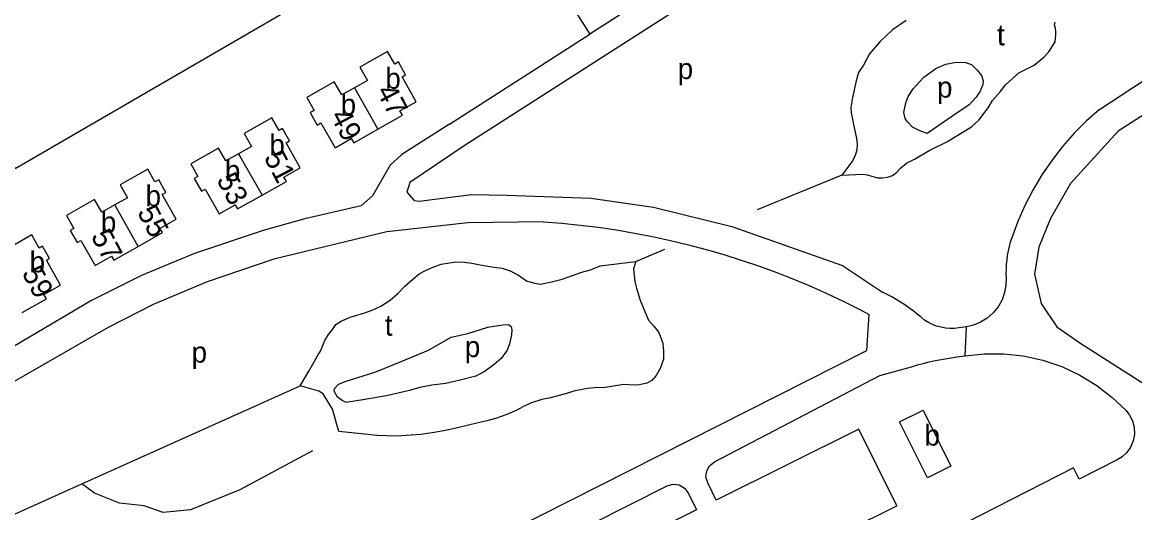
# Model space of a CAD drawing. Extents: x 158142 to 159655, y 385262 to 387204.
# Drawn here: x 158843.1 to 159056.3, y 386567 to 386661 of the extents above; entities that cross this region are included whole.
import ezdxf

# ---------------------------------------------------------------- set-up
doc = ezdxf.new("R2010")
doc.units = 0
for name, color, linetype in [('BLT_Basislijn', 7, 'Continuous'), ('BLT_Bebouwing', 7, 'Continuous'), ('BLT_Centroide', 7, 'Continuous'), ('BLT_Huisnummer', 7, 'Continuous'), ('BLT_Huisnummer_ tussenligend', 7, 'Continuous'), ('BLT_Onderverdeling_panden', 7, 'Continuous'), ('BLT_Vlakafsluiter', 7, 'Continuous')]:
    doc.layers.add(name, color=color, linetype=linetype)

msp = doc.modelspace()

# ---------------------------------------------------------------- linework, layer by layer
at = {"layer": 'BLT_Basislijn'}
for p, q in [((158962.1, 386665.28), (158951.94, 386658.76)), ((158925.01, 386641.49), (158951.94, 386658.76)), ((159000.23, 386631.69), (158983.98, 386625.1)), ((158960.72, 386615.19), (158966.31, 386617.55)), ((158854.55, 386572.55), (158896.42, 386591.34)), ((158826.78, 386560.1), (158854.55, 386572.55))]:
    msp.add_line(p, q, dxfattribs=at)
for points in [[(159032.59, 386711.15), (159035.58, 386706.39), (158927.86, 386637.32), (158917.44, 386630.31), (158916.87, 386628.46), (158918.23, 386626.84), (158919.19, 386626.73), (158929.27, 386628.01), (158936.03, 386627.86), (158952.13, 386627.33), (158964.14, 386625.61), (158979.12, 386621.87), (159000.33, 386614.38), (159008.02, 386609.31)], [(158800.5, 386644.91), (158826.35, 386660.11), (158841.79, 386632.99), (158934.18, 386686.67), (158951.94, 386658.76)], [(159049.58, 386644.33), (159081.97, 386665.65), (159105.75, 386680.86), (159110.71, 386684.88)], [(159012.56, 386661.36), (159009.93, 386659.58), (159007.5, 386657.27), (159005.54, 386654.96), (159004.35, 386652.83), (159003.4, 386651.37), (159002.96, 386649.79), (159002.25, 386646.61), (159001.96, 386644.66), (159002.03, 386643.66), (159002.17, 386642.74), (159002.37, 386641.76), (159003.04, 386638.74), (159003.12, 386637.64), (159003.06, 386636.57), (159002.8, 386635.68), (159002.3, 386634.54), (159000.23, 386631.69)], [(159000.23, 386631.69), (159004.24, 386631.89), (159005.05, 386631.75), (159006.39, 386631.37), (159007.03, 386631.23), (159008.02, 386631.19), (159008.96, 386631.32), (159009.93, 386631.65), (159010.61, 386632.19), (159011.51, 386633.14), (159012.59, 386634.04), (159014.16, 386634.8), (159017.05, 386636.52), (159020.31, 386638.09), (159025.04, 386640.96), (159026.45, 386642.28), (159028.23, 386644.63), (159029.09, 386646), (159030.56, 386647.7), (159031.59, 386649.06), (159034.14, 386651.35), (159037.07, 386652.79), (159039, 386654.42), (159039.89, 386655.34), (159041.1, 386657.25), (159041.25, 386658.59), (159041.24, 386659.28), (159041.14, 386659.88), (159040.99, 386660.5), (159041.1, 386661.07)], [(159085.3, 386660.77), (159053.17, 386640.17), (159044.04, 386630.1), (159040.22, 386623.44), (159037.96, 386617.94), (159037.14, 386612.74), (159038.41, 386607.15), (159041.39, 386602.67), (159045.98, 386599.46), (159059.02, 386591.14), (159060.49, 386588.42)], [(159049.58, 386644.33), (159047.1, 386642.12), (159044.74, 386639.74), (159042.52, 386637.21), (159040.46, 386634.55), (159038.55, 386631.76), (159036.82, 386628.87), (159035.28, 386625.88), (159033.92, 386622.83), (159032.76, 386619.71)], [(158925.01, 386641.49), (158915.91, 386635.65), (158913.62, 386633.64), (158910.28, 386627.76), (158908.07, 386625.82), (158897.31, 386623.34), (158889.29, 386621.08), (158876.15, 386616.73), (158865.98, 386612.5), (158856.4, 386607.67), (158835.4, 386595.28)], [(158943.04, 386622.77), (158928.51, 386622.6), (158913, 386620.87), (158891.33, 386615.63), (158878.55, 386611.27), (158868.25, 386606.92), (158859.58, 386602.5), (158828.64, 386584.76)], [(158943.04, 386622.77), (158946.54, 386622.49), (158950.05, 386622.15), (158953.54, 386621.72), (158957.02, 386621.21), (158960.49, 386620.62), (158963.94, 386619.95), (158967.38, 386619.21), (158970.8, 386618.38), (158974.2, 386617.48), (158977.58, 386616.5), (158980.94, 386615.45), (158984.27, 386614.32), (158987.57, 386613.11), (158990.85, 386611.83), (158994.1, 386610.48), (158997.31, 386609.05), (159000.49, 386607.55), (159003.64, 386605.97), (159005.43, 386605.04)], [(159032.76, 386619.71), (159032.5, 386618.89), (159032.27, 386618.05), (159032.08, 386617.2), (159031.92, 386616.35), (159031.81, 386615.49), (159031.72, 386614.62), (159031.68, 386613.76), (159031.67, 386612.89), (159031.7, 386612.03)], [(158896.42, 386591.34), (158898.09, 386594.17), (158899.89, 386597.41), (158900.27, 386598.01), (158900.7, 386598.93), (158901.16, 386600.05), (158901.83, 386601.16), (158902.61, 386602.16), (158903.25, 386603.07), (158904.27, 386603.75), (158905.97, 386604.5), (158907.28, 386604.87), (158908.63, 386605.27), (158910.21, 386605.82), (158911.85, 386606.62), (158913.62, 386607.75), (158915.12, 386609.01), (158916.49, 386610.47), (158917.98, 386611.8), (158919.19, 386612.79), (158920.4, 386613.46), (158921.99, 386614.15), (158923.41, 386614.63), (158925, 386614.93), (158926.24, 386615.08), (158927.92, 386615.05), (158929.31, 386614.88), (158930.91, 386614.53), (158933.53, 386614.11), (158935.09, 386613.89), (158936.68, 386613.35), (158938.24, 386612.54), (158939.78, 386611.48), (158941.29, 386611), (158942.49, 386610.81), (158944.54, 386611.24), (158946.62, 386611.77), (158950.41, 386613.15), (158952.07, 386613.58), (158953.9, 386614.32), (158957.53, 386614.78), (158960.72, 386615.19)], [(158960.72, 386615.19), (158960.27, 386613.75), (158960.57, 386611.32), (158960.84, 386610.04), (158961.57, 386607.73), (158962.46, 386605.59), (158963.18, 386603.91), (158964.27, 386602.69), (158965.12, 386601.58), (158965.91, 386599.54), (158966.05, 386597.91), (158966.04, 386596.46), (158965.4, 386594.67), (158964.63, 386593.3), (158963.8, 386592.39), (158962.87, 386591.85), (158961.44, 386591.54), (158960.4, 386591.48), (158958.42, 386591.62), (158954.88, 386591.03), (158952.74, 386590.94), (158951.45, 386590.83), (158950.43, 386590.65), (158948.88, 386590.31), (158947.43, 386589.88), (158946.04, 386589.49), (158944.39, 386589.05), (158942.72, 386588.69), (158940.56, 386588.01), (158939.09, 386587.34), (158937.94, 386586.66), (158935.99, 386585.81), (158933.81, 386585.08), (158932.18, 386584.6), (158928.93, 386583.88), (158926.33, 386583.22), (158923.95, 386582.72), (158921.71, 386582.35), (158919.51, 386582.04), (158914.85, 386581.68), (158911.08, 386581.81), (158909.34, 386582.01), (158903.81, 386582.57), (158902.62, 386586.88), (158900.78, 386589.78), (158900.01, 386590.32), (158896.42, 386591.34)], [(159031.7, 386612.03), (159031.67, 386610.65), (159031.41, 386609.23), (159030.91, 386607.83), (159030.16, 386606.5), (159029.2, 386605.31), (159028.05, 386604.3), (159026.78, 386603.52), (159025.45, 386602.97), (159024.11, 386602.66)], [(159015.4, 386604.47), (159014.65, 386605.1), (159013.87, 386605.7), (159013.08, 386606.29), (159012.28, 386606.85), (159011.45, 386607.39), (159010.61, 386607.91), (159009.76, 386608.4), (159008.9, 386608.87), (159008.02, 386609.31)], [(158936.78, 386563.59), (159005.02, 386598.11), (159005.43, 386605.04)], [(159024.11, 386602.66), (159022.65, 386602.43), (159021.81, 386602.33), (159020.95, 386602.32), (159020.08, 386602.39), (159019.22, 386602.55), (159018.38, 386602.78), (159017.57, 386603.1), (159016.79, 386603.5), (159016.07, 386603.95), (159015.4, 386604.47)], [(159013.57, 386595), (159014.68, 386595.33), (159015.81, 386595.63), (159016.94, 386595.91), (159018.08, 386596.17), (159019.22, 386596.4), (159020.37, 386596.6), (159021.52, 386596.78), (159022.68, 386596.93), (159023.83, 386597.06)], [(159023.83, 386597.06), (159027.47, 386597.46), (159031.21, 386597.48), (159034.99, 386597.08), (159038.73, 386596.26), (159042.37, 386595.02), (159045.84, 386593.39), (159049.07, 386591.41), (159052.03, 386589.13), (159054.67, 386586.59)], [(158944.95, 386561.15), (158966.73, 386572.16), (158967.88, 386572.49), (158969.02, 386572.33), (158970.07, 386571.73), (158970.76, 386570.82), (158972.38, 386567.56), (158945.07, 386553.98), (158952.37, 386539.31), (159010.75, 386568.35), (159003.45, 386583.02), (158976.14, 386569.43), (158974.5, 386572.74), (158974.17, 386573.92), (158974.34, 386575.03), (158974.87, 386575.98), (158975.83, 386576.76), (159007.51, 386593.32), (159013.57, 386595)], [(159054.67, 386586.59), (159055.36, 386585.71), (159055.89, 386584.64), (159056.22, 386583.42), (159056.28, 386582.1), (159056.05, 386580.79), (159055.54, 386579.58), (159054.81, 386578.54), (159053.94, 386577.72), (159052.99, 386577.13)], [(158898.74, 386578.89), (158884.81, 386571.43), (158875.37, 386567.59), (158870.16, 386567.05), (158866.53, 386568.31), (158861.8, 386568.87), (158856.97, 386570.76), (158854.55, 386572.55)], [(159052.99, 386577.13), (159045.69, 386573.45), (159044.58, 386575.63), (158991.36, 386548.38)]]:
    msp.add_lwpolyline(points, dxfattribs=at)
for points in [[(159016.58, 386639.73), (159015.02, 386640.25), (159013.76, 386640.93), (159012.79, 386641.91), (159012.33, 386642.55), (159012.1, 386643.7), (159012.45, 386645.6), (159012.92, 386646.77), (159013.86, 386648.28), (159015.07, 386649.62), (159015.93, 386650.52), (159018.25, 386652.15), (159020.15, 386652.97), (159022.1, 386653.37), (159023.92, 386653.31), (159025.04, 386652.95), (159026.1, 386651.91), (159026.98, 386650.81), (159027.27, 386649.8), (159027.23, 386649.08), (159026.69, 386647.8), (159025.93, 386646.68), (159024.58, 386645.2), (159021.49, 386643.06)], [(158902.92, 386590.33), (158903.06, 386590.87), (158903.78, 386591.64), (158905.23, 386592.22), (158910.88, 386593.99), (158915.76, 386596.01), (158921, 386598.18), (158925.37, 386600.64), (158928.51, 386601.39), (158932.35, 386602.55), (158935.26, 386603), (158936.34, 386603.07), (158936.83, 386602.68), (158936.94, 386602.08), (158936.89, 386601.14), (158936.54, 386599.37), (158936.07, 386598.15), (158934.94, 386596.57), (158933.61, 386595.41), (158931.85, 386594.12), (158930.05, 386593.22), (158927.04, 386592.42), (158924.35, 386591.77), (158921.61, 386591.44), (158919.36, 386591.01), (158917.33, 386590.46), (158912.96, 386589.4), (158908.8, 386588.72), (158905.23, 386588.12), (158904.46, 386588.54), (158903.58, 386589.18)]]:
    msp.add_lwpolyline(points, close=True, dxfattribs=at)
at = {"layer": 'BLT_Bebouwing'}
for points in [[(158911.31, 386640.55), (158915.99, 386643.21), (158915.52, 386644.04), (158918.62, 386645.8), (158915.92, 386650.58), (158916.61, 386650.97), (158915.23, 386653.41), (158914.53, 386653.01), (158913.16, 386655.45), (158907.83, 386652.43), (158909.28, 386649.87), (158906.82, 386648.48)], [(158906.82, 386648.48), (158904.36, 386647.09), (158902.94, 386649.6), (158897.65, 386646.61), (158899.06, 386644.12), (158898.32, 386643.71), (158899.68, 386641.32)], [(158889.1, 386627.88), (158893.76, 386630.52), (158893.3, 386631.35), (158896.42, 386633.11), (158893.69, 386637.93), (158894.35, 386638.3), (158893.04, 386640.63), (158892.37, 386640.25), (158890.99, 386642.69), (158885.68, 386639.69), (158887.07, 386637.23), (158884.6, 386635.83)], [(158899.68, 386641.32), (158900.39, 386641.72), (158903.08, 386636.96), (158906.2, 386638.73), (158906.66, 386637.93), (158911.31, 386640.55)], [(158884.6, 386635.83), (158882.13, 386634.44), (158880.74, 386636.9), (158875.43, 386633.9), (158876.82, 386631.45), (158876.12, 386631.05), (158877.48, 386628.66)], [(158865.35, 386618.07), (158869.99, 386620.7), (158869.53, 386621.52), (158872.66, 386623.29), (158869.98, 386628.03), (158870.68, 386628.42), (158869.31, 386630.84), (158868.58, 386630.43), (158867.19, 386632.88), (158861.9, 386629.89), (158863.32, 386627.39), (158860.86, 386626)], [(158877.48, 386628.66), (158878.18, 386629.06), (158880.87, 386624.29), (158883.96, 386626.04), (158884.42, 386625.24), (158889.1, 386627.88)], [(158860.86, 386626), (158858.4, 386624.61), (158857.02, 386627.05), (158851.65, 386624.01), (158853.06, 386621.52), (158852.34, 386621.11), (158853.65, 386618.8)], [(158843.11, 386605.37), (158847.77, 386608.01), (158847.3, 386608.84), (158850.48, 386610.64), (158847.77, 386615.42), (158848.36, 386615.75), (158847.03, 386618.11), (158846.41, 386617.75), (158844.99, 386620.25), (158839.65, 386617.23), (158841.07, 386614.72), (158838.6, 386613.33)], [(158853.65, 386618.8), (158854.39, 386619.21), (158857.1, 386614.42), (158860.27, 386616.21), (158860.7, 386615.44), (158865.35, 386618.07)]]:
    msp.add_lwpolyline(points, dxfattribs=at)
msp.add_lwpolyline([(159011.29, 386584.45), (159015.77, 386586.67), (159021.1, 386575.91), (159016.61, 386573.69)], close=True, dxfattribs=at)
at = {"layer": 'BLT_Onderverdeling_panden'}
for p, q in [((158906.82, 386648.48), (158911.31, 386640.55)), ((158884.6, 386635.83), (158889.1, 386627.88)), ((158865.35, 386618.07), (158860.86, 386626))]:
    msp.add_line(p, q, dxfattribs=at)
at = {"layer": 'BLT_Vlakafsluiter'}
msp.add_line((159023.83, 386597.06), (159024.11, 386602.66), dxfattribs=at)

# ---------------------------------------------------------------- texts
at = {"layer": 'BLT_Centroide'}
for s, p in [('t', (159029.95, 386656.6)), ('b', (158912.72, 386648.27)), ('p', (158968.75, 386650.13)), ('p', (159018.44, 386646.58)), ('b', (158904.16, 386643.28)), ('b', (158890.5, 386635.55)), ('b', (158881.97, 386630.59)), ('b', (158866.77, 386625.75)), ('b', (158858.2, 386620.72)), ('b', (158844.55, 386613.09)), ('t', (158912.63, 386600.95)), ('p', (158875.59, 386595.79)), ('p', (158927.95, 386596.84)), ('b', (159016.05, 386579.88))]:
    msp.add_text(s, height=4, dxfattribs=at).set_placement(p)
at = {"layer": 'BLT_Huisnummer'}
for s, p in [('47', (158910.91, 386647.82)), ('51', (158889.37, 386635.11)), ('55', (158865.09, 386624.66)), ('59', (158842.99, 386612.99))]:
    msp.add_text(s, height=4, rotation=297.8252, dxfattribs=at).set_placement(p)
at = {"layer": 'BLT_Huisnummer_ tussenligend'}
for s, p in [('49', (158902.09, 386643.1)), ('53', (158880.3, 386630.87)), ('57', (158856.22, 386620.04))]:
    msp.add_text(s, height=4, rotation=297.8252, dxfattribs=at).set_placement(p)

doc.saveas('drawing.dxf')
